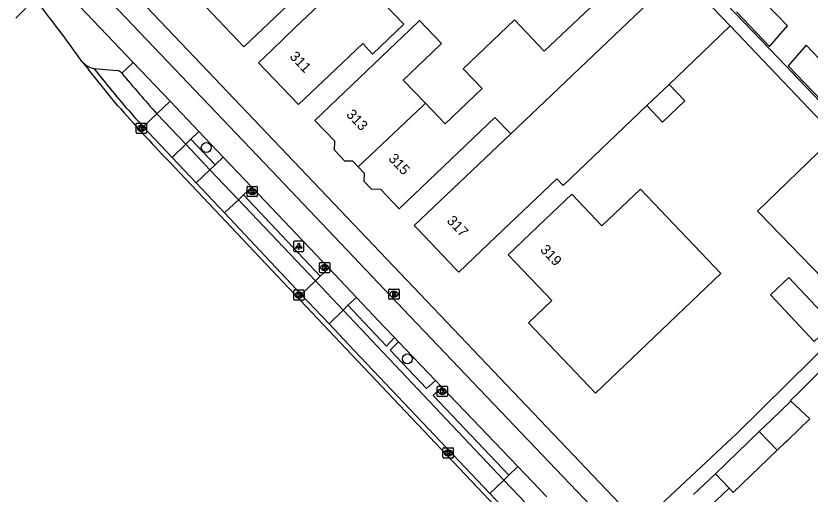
# Model space of a CAD drawing. Extents: x 162532 to 163264, y 381233 to 382042.
# Drawn here: x 162887.1 to 162964.6, y 381456.6 to 381503.3 of the extents above; entities that cross this region are included whole.
import ezdxf

# ---------------------------------------------------------------- set-up
doc = ezdxf.new("R2010")
doc.units = 0
for name, color, linetype in [('IMGEO_Berm_open', 7, 'Continuous'), ('IMGEO_Boom', 7, 'Continuous'), ('IMGEO_Brandkraan', 7, 'Continuous'), ('IMGEO_Fietspad_gesloten', 7, 'Continuous'), ('IMGEO_Kolk', 7, 'Continuous'), ('IMGEO_Lichtpunt', 7, 'Continuous'), ('IMGEO_Pand', 7, 'Continuous'), ('IMGEO_Pand_nummerreeks', 7, 'Continuous'), ('IMGEO_Parkeervlak_open', 7, 'Continuous'), ('IMGEO_Rijbaan_lokaal_gesloten', 7, 'Continuous'), ('IMGEO_Rijbaan_lokaal_open', 7, 'Continuous'), ('IMGEO_Voetpad_open', 7, 'Continuous')]:
    doc.layers.add(name, color=color, linetype=linetype)

msp = doc.modelspace()

# ---------------------------------------------------------------- linework, layer by layer
at = {"layer": 'IMGEO_Berm_open'}
for points in [[(162904.184, 381491.264), (162906.542, 381488.775)], [(162909.305, 381485.832), (162916.791, 381477.899)], [(162924.045, 381471.906), (162923.253, 381471.075), (162919.487, 381475.057)], [(162928.036, 381467.73), (162927.177, 381466.938), (162923.617, 381470.677), (162924.447, 381471.486)], [(162935.188, 381458.474), (162927.816, 381466.266), (162928.672, 381467.066)]]:
    msp.add_lwpolyline(points, dxfattribs=at)
at = {"layer": 'IMGEO_Boom'}
for centre in [(162905.684, 381490.454), (162925.296, 381469.827)]:
    msp.add_circle(centre, 0.489, dxfattribs=at)
at = {"layer": 'IMGEO_Brandkraan'}
for p, q in [((162923.496, 381475.723), (162923.496, 381476.575)), ((162923.571, 381476.649), (162924.423, 381476.649)), ((162923.984, 381476.429), (162924.009, 381476.429)), ((162924.497, 381476.575), (162924.497, 381475.723)), ((162924.423, 381475.649), (162923.571, 381475.649)), ((162924.007, 381475.869), (162923.982, 381475.869))]:
    msp.add_line(p, q, dxfattribs=at)
for points in [[(162923.496, 381475.723), (162923.496, 381476.575)], [(162923.571, 381476.649), (162924.423, 381476.649)], [(162923.844, 381476.349), (162923.844, 381475.949), (162924.057, 381475.949)], [(162924.075, 381476.349), (162923.844, 381476.349)], [(162924.023, 381476.268), (162923.969, 381476.268), (162923.969, 381476.192)], [(162923.969, 381476.192), (162924.022, 381476.192)], [(162924.031, 381476.116), (162923.969, 381476.116), (162923.969, 381476.035)], [(162923.969, 381476.035), (162924.031, 381476.035)], [(162924.497, 381476.575), (162924.497, 381475.723)], [(162924.423, 381475.649), (162923.571, 381475.649)]]:
    msp.add_lwpolyline(points, dxfattribs=at)
for centre, radius, start, end in [((162923.573, 381476.573), 0.0765, 91.55205, 178.44795), ((162923.573, 381476.573), 0.0765, 91.55205, 178.44795), ((162924.024, 381476.23), 0.0379, 267.82845, 90.93552), ((162924.032, 381476.075), 0.0404, 269.87594, 90.50774), ((162924.063, 381476.2), 0.251, 268.66757, 293.53466), ((162924.079, 381476.204), 0.145, 59.4692, 91.53667), ((162924.104, 381476.251), 0.0922, 285.51372, 58.15012), ((162924.109, 381476.059), 0.105, 301.31148, 78.98903), ((162924.421, 381476.573), 0.0765, 1.55205, 88.44795), ((162924.421, 381476.573), 0.0765, 1.55205, 88.44795), ((162923.573, 381475.725), 0.0765, 181.55205, 268.44795), ((162923.573, 381475.725), 0.0765, 181.55205, 268.44795), ((162924.421, 381475.725), 0.0765, 271.55205, 358.44795), ((162924.421, 381475.725), 0.0765, 271.55205, 358.44795)]:
    msp.add_arc(centre, radius, start, end, dxfattribs=at)
for centre, major_axis, ratio, start_param, end_param in [((162923.983, 381476.149), (-0.387, 0.002), 0.722429, 4.712389, 7.853982), ((162924.008, 381476.149), (-0.39, 0.002), 0.717154, 1.570796, 4.712389)]:
    msp.add_ellipse(centre, major_axis=major_axis, ratio=ratio, start_param=start_param, end_param=end_param, dxfattribs=at)
at = {"layer": 'IMGEO_Fietspad_gesloten'}
for points in [[(162888.028, 381513.353), (162891.8, 381509.488), (162912.667, 381487.562), (162924.904, 381474.653), (162959.423, 381438.485), (162961.518, 381436.339)], [(162889.27, 381508.508), (162895.973, 381501.441), (162898.543, 381498.758)], [(162898.543, 381498.758), (162902.145, 381494.967)], [(162904.958, 381492.006), (162907.318, 381489.521)], [(162910.115, 381486.578), (162917.623, 381478.675)], [(162920.321, 381475.835), (162923.037, 381472.961), (162924.045, 381471.906)], [(162924.447, 381471.486), (162924.045, 381471.906)], [(162924.447, 381471.486), (162928.036, 381467.73)], [(162928.672, 381467.066), (162928.036, 381467.73)], [(162928.672, 381467.066), (162936.08, 381459.315)]]:
    msp.add_lwpolyline(points, dxfattribs=at)
at = {"layer": 'IMGEO_Kolk'}
for p, q in [((162898.849, 381491.909), (162898.849, 381492.761)), ((162898.924, 381492.835), (162899.776, 381492.835)), ((162899.337, 381492.615), (162899.362, 381492.615)), ((162899.85, 381492.761), (162899.85, 381491.909)), ((162899.776, 381491.835), (162898.924, 381491.835)), ((162899.36, 381492.055), (162899.335, 381492.055)), ((162909.658, 381485.737), (162909.658, 381486.589)), ((162909.733, 381486.663), (162910.585, 381486.663)), ((162910.146, 381486.443), (162910.171, 381486.443)), ((162910.659, 381486.589), (162910.659, 381485.737)), ((162910.585, 381485.663), (162909.733, 381485.663)), ((162910.169, 381485.883), (162910.144, 381485.883)), ((162916.726, 381478.316), (162916.726, 381479.168)), ((162916.801, 381479.242), (162917.653, 381479.242)), ((162917.214, 381479.022), (162917.239, 381479.022)), ((162917.727, 381479.168), (162917.727, 381478.316)), ((162917.237, 381478.462), (162917.212, 381478.462)), ((162917.653, 381478.242), (162916.801, 381478.242)), ((162914.23, 381475.63), (162914.23, 381476.482)), ((162914.305, 381476.556), (162915.157, 381476.556)), ((162914.718, 381476.336), (162914.743, 381476.336)), ((162915.231, 381476.482), (162915.231, 381475.63)), ((162915.157, 381475.556), (162914.305, 381475.556)), ((162914.741, 381475.776), (162914.716, 381475.776)), ((162928.203, 381466.232), (162928.203, 381467.084)), ((162928.278, 381467.158), (162929.13, 381467.158)), ((162928.691, 381466.938), (162928.716, 381466.938)), ((162929.204, 381467.084), (162929.204, 381466.232)), ((162929.13, 381466.158), (162928.278, 381466.158)), ((162928.714, 381466.378), (162928.689, 381466.378)), ((162928.772, 381460.232), (162928.772, 381461.084)), ((162928.847, 381461.158), (162929.699, 381461.158)), ((162929.26, 381460.938), (162929.285, 381460.938)), ((162929.773, 381461.084), (162929.773, 381460.232)), ((162929.699, 381460.158), (162928.847, 381460.158)), ((162929.283, 381460.378), (162929.258, 381460.378))]:
    msp.add_line(p, q, dxfattribs=at)
for points in [[(162898.849, 381491.909), (162898.849, 381492.761)], [(162898.924, 381492.835), (162899.776, 381492.835)], [(162899.17, 381492.535), (162899.293, 381492.535), (162899.293, 381492.384), (162899.423, 381492.535), (162899.587, 381492.535), (162899.441, 381492.384), (162899.594, 381492.135), (162899.442, 381492.135), (162899.357, 381492.299), (162899.293, 381492.232), (162899.293, 381492.135), (162899.17, 381492.135), (162899.17, 381492.535)], [(162899.85, 381492.761), (162899.85, 381491.909)], [(162899.776, 381491.835), (162898.924, 381491.835)], [(162909.658, 381485.737), (162909.658, 381486.589)], [(162909.733, 381486.663), (162910.585, 381486.663)], [(162909.979, 381486.363), (162910.102, 381486.363), (162910.102, 381486.212), (162910.232, 381486.363), (162910.396, 381486.363), (162910.25, 381486.212), (162910.403, 381485.963), (162910.251, 381485.963), (162910.166, 381486.127), (162910.102, 381486.06), (162910.102, 381485.963), (162909.979, 381485.963), (162909.979, 381486.363)], [(162910.659, 381486.589), (162910.659, 381485.737)], [(162910.585, 381485.663), (162909.733, 381485.663)], [(162916.726, 381478.316), (162916.726, 381479.168)], [(162916.801, 381479.242), (162917.653, 381479.242)], [(162917.727, 381479.168), (162917.727, 381478.316)], [(162917.047, 381478.942), (162917.17, 381478.942), (162917.17, 381478.791), (162917.3, 381478.942), (162917.464, 381478.942), (162917.318, 381478.791), (162917.471, 381478.542), (162917.319, 381478.542), (162917.234, 381478.706), (162917.17, 381478.639), (162917.17, 381478.542), (162917.047, 381478.542), (162917.047, 381478.942)], [(162917.653, 381478.242), (162916.801, 381478.242)], [(162914.23, 381475.63), (162914.23, 381476.482)], [(162914.305, 381476.556), (162915.157, 381476.556)], [(162914.551, 381476.256), (162914.674, 381476.256), (162914.674, 381476.105), (162914.804, 381476.256), (162914.968, 381476.256), (162914.822, 381476.105), (162914.975, 381475.856), (162914.823, 381475.856), (162914.738, 381476.02), (162914.674, 381475.953), (162914.674, 381475.856), (162914.551, 381475.856), (162914.551, 381476.256)], [(162915.231, 381476.482), (162915.231, 381475.63)], [(162915.157, 381475.556), (162914.305, 381475.556)], [(162928.203, 381466.232), (162928.203, 381467.084)], [(162928.278, 381467.158), (162929.13, 381467.158)], [(162928.524, 381466.858), (162928.647, 381466.858), (162928.647, 381466.707), (162928.777, 381466.858), (162928.941, 381466.858), (162928.795, 381466.707), (162928.948, 381466.458), (162928.796, 381466.458), (162928.711, 381466.622), (162928.647, 381466.555), (162928.647, 381466.458), (162928.524, 381466.458), (162928.524, 381466.858)], [(162929.204, 381467.084), (162929.204, 381466.232)], [(162929.13, 381466.158), (162928.278, 381466.158)], [(162928.772, 381460.232), (162928.772, 381461.084)], [(162928.847, 381461.158), (162929.699, 381461.158)], [(162929.093, 381460.858), (162929.216, 381460.858), (162929.216, 381460.707), (162929.346, 381460.858), (162929.51, 381460.858), (162929.364, 381460.707), (162929.517, 381460.458), (162929.365, 381460.458), (162929.28, 381460.622), (162929.216, 381460.555), (162929.216, 381460.458), (162929.093, 381460.458), (162929.093, 381460.858)], [(162929.773, 381461.084), (162929.773, 381460.232)], [(162929.699, 381460.158), (162928.847, 381460.158)]]:
    msp.add_lwpolyline(points, dxfattribs=at)
for centre, start, end in [((162898.926, 381492.759), 91.55205, 178.44795), ((162898.926, 381492.759), 91.55205, 178.44795), ((162899.774, 381492.759), 1.55205, 88.44795), ((162899.774, 381492.759), 1.55205, 88.44795), ((162898.926, 381491.911), 181.55205, 268.44795), ((162898.926, 381491.911), 181.55205, 268.44795), ((162899.774, 381491.911), 271.55205, 358.44795), ((162899.774, 381491.911), 271.55205, 358.44795), ((162909.735, 381486.587), 91.55205, 178.44795), ((162909.735, 381486.587), 91.55205, 178.44795), ((162910.583, 381486.587), 1.55205, 88.44795), ((162910.583, 381486.587), 1.55205, 88.44795), ((162909.735, 381485.739), 181.55205, 268.44795), ((162909.735, 381485.739), 181.55205, 268.44795), ((162910.583, 381485.739), 271.55205, 358.44795), ((162910.583, 381485.739), 271.55205, 358.44795), ((162916.803, 381479.166), 91.55205, 178.44795), ((162916.803, 381479.166), 91.55205, 178.44795), ((162917.651, 381479.166), 1.55205, 88.44795), ((162917.651, 381479.166), 1.55205, 88.44795), ((162916.803, 381478.318), 181.55205, 268.44795), ((162916.803, 381478.318), 181.55205, 268.44795), ((162917.651, 381478.318), 271.55205, 358.44795), ((162917.651, 381478.318), 271.55205, 358.44795), ((162914.307, 381476.48), 91.55205, 178.44795), ((162914.307, 381476.48), 91.55205, 178.44795), ((162915.155, 381476.48), 1.55205, 88.44795), ((162915.155, 381476.48), 1.55205, 88.44795), ((162914.307, 381475.632), 181.55205, 268.44795), ((162914.307, 381475.632), 181.55205, 268.44795), ((162915.155, 381475.632), 271.55205, 358.44795), ((162915.155, 381475.632), 271.55205, 358.44795), ((162928.28, 381467.082), 91.55205, 178.44795), ((162928.28, 381467.082), 91.55205, 178.44795), ((162929.128, 381467.082), 1.55205, 88.44795), ((162929.128, 381467.082), 1.55205, 88.44795), ((162928.28, 381466.234), 181.55205, 268.44795), ((162928.28, 381466.234), 181.55205, 268.44795), ((162929.128, 381466.234), 271.55205, 358.44795), ((162929.128, 381466.234), 271.55205, 358.44795), ((162928.849, 381461.082), 91.55205, 178.44795), ((162928.849, 381461.082), 91.55205, 178.44795), ((162929.697, 381461.082), 1.55205, 88.44795), ((162929.697, 381461.082), 1.55205, 88.44795), ((162928.849, 381460.234), 181.55205, 268.44795), ((162928.849, 381460.234), 181.55205, 268.44795), ((162929.697, 381460.234), 271.55205, 358.44795), ((162929.697, 381460.234), 271.55205, 358.44795)]:
    msp.add_arc(centre, 0.0765, start, end, dxfattribs=at)
for centre, major_axis, ratio, start_param, end_param in [((162899.336, 381492.335), (-0.387, 0.002), 0.722429, 4.712389, 7.853982), ((162899.361, 381492.335), (-0.39, 0.002), 0.717154, 1.570796, 4.712389), ((162910.145, 381486.163), (-0.387, 0.002), 0.722429, 4.712389, 7.853982), ((162910.17, 381486.163), (-0.39, 0.002), 0.717154, 1.570796, 4.712389), ((162917.213, 381478.742), (-0.387, 0.002), 0.722429, 4.712389, 7.853982), ((162917.238, 381478.742), (-0.39, 0.002), 0.717154, 1.570796, 4.712389), ((162914.717, 381476.056), (-0.387, 0.002), 0.722429, 4.712389, 7.853982), ((162914.742, 381476.056), (-0.39, 0.002), 0.717154, 1.570796, 4.712389), ((162928.69, 381466.658), (-0.387, 0.002), 0.722429, 4.712389, 7.853982), ((162928.715, 381466.658), (-0.39, 0.002), 0.717154, 1.570796, 4.712389), ((162929.259, 381460.658), (-0.387, 0.002), 0.722429, 4.712389, 7.853982), ((162929.284, 381460.658), (-0.39, 0.002), 0.717154, 1.570796, 4.712389)]:
    msp.add_ellipse(centre, major_axis=major_axis, ratio=ratio, start_param=start_param, end_param=end_param, dxfattribs=at)
at = {"layer": 'IMGEO_Lichtpunt'}
for p, q in [((162914.202, 381481.221), (162914.202, 381480.414)), ((162914.202, 381481.221), (162914.202, 381480.414)), ((162915.104, 381481.316), (162914.296, 381481.316)), ((162915.104, 381481.316), (162914.296, 381481.316)), ((162915.198, 381480.414), (162915.198, 381481.221)), ((162915.198, 381480.414), (162915.198, 381481.221)), ((162914.296, 381480.32), (162915.104, 381480.32)), ((162914.296, 381480.32), (162915.104, 381480.32))]:
    msp.add_line(p, q, dxfattribs=at)
for points in [[(162914.576, 381480.885), (162914.615, 381480.857), (162914.427, 381480.595), (162914.389, 381480.622), (162914.576, 381480.885)], [(162914.678, 381480.837), (162914.725, 381480.837), (162914.725, 381480.515), (162914.678, 381480.515), (162914.678, 381480.837)], [(162914.788, 381480.857), (162914.826, 381480.884), (162915.013, 381480.622), (162914.974, 381480.594), (162914.788, 381480.857)]]:
    msp.add_lwpolyline(points, dxfattribs=at)
msp.add_circle((162914.701, 381481.019), 0.0994, dxfattribs=at)
for centre, start, end in [((162914.296, 381481.221), 90, 180), ((162914.296, 381481.221), 90, 180), ((162915.104, 381481.221), 0, 90), ((162915.104, 381481.221), 0, 90), ((162914.296, 381480.414), 180, 270), ((162914.296, 381480.414), 180, 270), ((162915.104, 381480.414), 270, 0), ((162915.104, 381480.414), 270, 360)]:
    msp.add_arc(centre, 0.0946, start, end, dxfattribs=at)
at = {"layer": 'IMGEO_Pand'}
for points in [[(162927.06, 381494.771), (162928.973, 381492.767), (162931.838, 381495.502), (162932.581, 381496.211), (162930.729, 381498.15), (162935.735, 381502.902), (162938.652, 381499.847), (162944.855, 381505.737), (162941.842, 381508.894), (162946.401, 381513.222)], [(162915.003, 381512.983), (162916.796, 381511.073), (162915.915, 381510.232), (162913.74, 381508.157), (162915.584, 381506.224), (162912.972, 381503.732), (162909.354, 381500.28), (162905.639, 381504.174)], [(162923.972, 381503.5), (162924.946, 381502.479), (162921.897, 381499.569), (162920.938, 381500.605), (162920.304, 381500), (162918.305, 381498.093), (162914.687, 381494.641), (162910.779, 381498.736), (162912.104, 381500), (162914.397, 381502.188), (162920.065, 381507.596), (162921.066, 381508.551), (162922.916, 381506.613), (162921.914, 381505.657), (162922.01, 381505.557), (162923.972, 381503.5)], [(162935.374, 381491.799), (162948.134, 381503.914), (162951.885, 381507.475)], [(162956.799, 381502.326), (162951.885, 381507.475)], [(162957.395, 381503.695), (162960.624, 381500.325), (162962.39, 381502.325), (162959.161, 381505.694)], [(162920.503, 381488.564), (162919.981, 381489.111), (162919.209, 381489.129), (162918.187, 381490.2), (162918.208, 381491.09), (162916.28, 381493.109), (162919.897, 381496.562), (162923.5, 381500), (162925.574, 381501.979), (162926.488, 381502.852), (162928.636, 381500.6), (162927.722, 381499.728), (162924.9, 381497.035), (162927.06, 381494.771)], [(162956.799, 381502.326), (162954.918, 381500.53), (162950.818, 381496.616)], [(162967.45, 381497.045), (162964.205, 381500.432), (162962.438, 381498.432), (162965.683, 381495.045)], [(162950.818, 381496.616), (162952.35, 381495.012), (162950.188, 381492.947), (162948.656, 381494.551)], [(162948.656, 381494.551), (162950.818, 381496.616)], [(162927.06, 381494.771), (162926.828, 381494.547), (162920.503, 381488.564)], [(162948.656, 381494.551), (162940.499, 381486.762), (162939.885, 381487.405), (162933.973, 381481.762), (162930.329, 381478.283), (162929.997, 381478.63), (162926.338, 381482.463), (162925.959, 381482.861), (162935.374, 381491.799)], [(162935.374, 381491.799), (162935.349, 381491.825), (162933.844, 381493.401), (162928.117, 381487.935), (162924.5, 381484.482), (162922.707, 381486.36), (162921.802, 381486.381), (162921.086, 381487.132), (162921.104, 381487.935), (162920.503, 381488.564)], [(162966.696, 381491.253), (162966.876, 381491.427), (162976.591, 381481.38), (162976.41, 381481.206), (162969.171, 381474.207), (162968.934, 381474.452), (162959.589, 381484.117), (162959.457, 381484.253), (162966.311, 381490.881), (162966.696, 381491.253)], [(162955.887, 381478.162), (162947.271, 381469.938), (162943.662, 381466.493), (162937.109, 381473.359), (162939.379, 381475.525), (162935.131, 381479.974), (162938.748, 381483.427), (162941.33, 381485.891), (162944.272, 381482.808), (162948.029, 381486.394), (162955.887, 381478.162)], [(162962.511, 381477.771), (162966.788, 381473.217), (162964.984, 381471.523), (162960.707, 381476.077), (162962.511, 381477.771)], [(162962.685, 381465.697), (162960.778, 381463.861), (162959.627, 381462.753)], [(162961.372, 381460.924), (162962.212, 381461.733), (162962.4, 381461.915), (162964.543, 381463.977), (162962.685, 381465.697)], [(162955.345, 381458.629), (162959.627, 381462.753)], [(162959.627, 381462.753), (162961.372, 381460.924)], [(162961.372, 381460.924), (162957.089, 381456.801), (162956.684, 381457.226)], [(162953.201, 381456.583), (162955.345, 381458.629)], [(162956.684, 381457.226), (162955.345, 381458.629)], [(162956.684, 381457.226), (162954.837, 381455.462), (162954.541, 381455.18)]]:
    msp.add_lwpolyline(points, dxfattribs=at)
at = {"layer": 'IMGEO_Parkeervlak_open'}
for points in [[(162894.726, 381498.173), (162896.997, 381497.958)], [(162906.04, 381488.29), (162903.687, 381490.773)], [(162916.32, 381477.446), (162908.814, 381485.363)], [(162934.705, 381458.004), (162919.021, 381474.596)]]:
    msp.add_lwpolyline(points, dxfattribs=at)
msp.add_arc((162896.897, 381497.258), 0.707, 39.29666, 81.87835, dxfattribs=at)
at = {"layer": 'IMGEO_Rijbaan_lokaal_gesloten'}
for points in [[(162887.11, 381503.092), (162888.972, 381504.997)], [(162893.553, 381498.859), (162893.123, 381499.458)], [(162897.034, 381494.573), (162894.209, 381498.061)], [(162957.731, 381430.254), (162919.892, 381470.214), (162901.988, 381489.161)]]:
    msp.add_lwpolyline(points, dxfattribs=at)
for centre, radius, start, end in [((162751.131, 381396.99), 175.104, 35.81589, 37.85399), ((162900.233, 381503.681), 8.238, 215.82756, 223.01662), ((163001.949, 381585.636), 138.923, 220.95697, 223.98333)]:
    msp.add_arc(centre, radius, start, end, dxfattribs=at)
at = {"layer": 'IMGEO_Rijbaan_lokaal_open'}
for points in [[(162894.726, 381498.173), (162895.836, 381496.785)], [(162900.875, 381493.741), (162902.145, 381494.967)], [(162902.145, 381494.967), (162904.958, 381492.006)], [(162900.875, 381493.741), (162899.535, 381492.474)], [(162903.687, 381490.773), (162900.875, 381493.741)], [(162899.535, 381492.474), (162902.368, 381489.469)], [(162904.958, 381492.006), (162904.184, 381491.264)], [(162902.368, 381489.469), (162903.687, 381490.773)], [(162903.687, 381490.773), (162904.184, 381491.264)], [(162902.368, 381489.469), (162904.702, 381486.995)], [(162906.542, 381488.775), (162907.318, 381489.521)], [(162907.318, 381489.521), (162910.115, 381486.578)], [(162906.542, 381488.775), (162906.04, 381488.29)], [(162906.04, 381488.29), (162904.702, 381486.995)], [(162906.04, 381488.29), (162908.814, 381485.363)], [(162904.702, 381486.995), (162907.46, 381484.07)], [(162910.115, 381486.578), (162909.305, 381485.832)], [(162908.814, 381485.363), (162907.46, 381484.07)], [(162908.814, 381485.363), (162909.305, 381485.832)], [(162907.46, 381484.07), (162914.949, 381476.128)], [(162916.791, 381477.899), (162917.623, 381478.675)], [(162917.623, 381478.675), (162920.321, 381475.835)], [(162916.791, 381477.899), (162916.32, 381477.446)], [(162914.949, 381476.128), (162916.32, 381477.446)], [(162916.32, 381477.446), (162919.021, 381474.596)], [(162914.949, 381476.128), (162917.662, 381473.25)], [(162919.487, 381475.057), (162920.321, 381475.835)], [(162919.021, 381474.596), (162917.662, 381473.25)], [(162919.487, 381475.057), (162919.021, 381474.596)], [(162917.662, 381473.25), (162920.135, 381470.628), (162933.348, 381456.685)], [(162935.188, 381458.474), (162936.08, 381459.315)], [(162936.08, 381459.315), (162938.891, 381456.375)], [(162934.705, 381458.004), (162935.188, 381458.474)], [(162933.348, 381456.685), (162934.705, 381458.004)], [(162934.705, 381458.004), (162937.492, 381455.055)], [(162933.348, 381456.685), (162936.131, 381453.749)]]:
    msp.add_lwpolyline(points, dxfattribs=at)
for centre, radius, start, end in [((162895.072, 381500.111), 1.968, 219.4851, 259.87455), ((162967.973, 381554.939), 92.659, 218.8743, 222.38736)]:
    msp.add_arc(centre, radius, start, end, dxfattribs=at)
at = {"layer": 'IMGEO_Voetpad_open'}
for points in [[(162939.444, 381522.425), (162939.321, 381522.307), (162944.847, 381516.541), (162948.991, 381512.217), (162953.136, 381507.892), (162957.281, 381503.566), (162961.425, 381499.243), (162965.57, 381494.917), (162969.718, 381490.59), (162973.859, 381486.269), (162977.616, 381482.348), (162977.739, 381482.466)], [(162947.952, 381453.669), (162903.859, 381500), (162892.594, 381511.832)], [(162947.952, 381453.669), (162957.442, 381462.564), (162967.253, 381472.252), (162976.751, 381481.351), (162956.799, 381502.326)], [(162898.543, 381498.758), (162897.444, 381497.706)], [(162985.898, 381488.614), (162984.752, 381487.882), (162980.521, 381483.642), (162976.289, 381479.402), (162972.042, 381475.147), (162967.82, 381470.916), (162963.597, 381466.685), (162962.644, 381465.731), (162962.685, 381465.697)]]:
    msp.add_lwpolyline(points, dxfattribs=at)
msp.add_arc((163000.293, 381583.237), 133.766, 219.74733, 221.99336, dxfattribs=at)

# ---------------------------------------------------------------- texts
at = {"layer": 'IMGEO_Pand_nummerreeks'}
for s, rotation, p in [('311', 313.65917, (162913.747, 381499.277)), ('313', 313.61334, (162919.272, 381493.622)), ('315', 313.61334, (162923.382, 381489.308)), ('317', 313.67063, (162929.079, 381483.243)), ('319', 313.67605, (162938.188, 381480.421))]:
    msp.add_text(s, height=1, rotation=rotation, dxfattribs=at).set_placement(p)

doc.saveas('drawing.dxf')
